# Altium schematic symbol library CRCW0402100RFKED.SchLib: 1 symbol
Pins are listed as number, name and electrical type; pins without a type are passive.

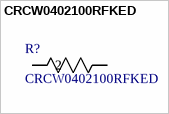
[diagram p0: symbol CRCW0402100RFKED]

## CRCW0402100RFKED
designator R?
D10/CRCW0402 100 100R 1% ET7 e3; Manufacturer_Name: Vishay
footprint RES_CRCW_0402
pins: 1, 2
